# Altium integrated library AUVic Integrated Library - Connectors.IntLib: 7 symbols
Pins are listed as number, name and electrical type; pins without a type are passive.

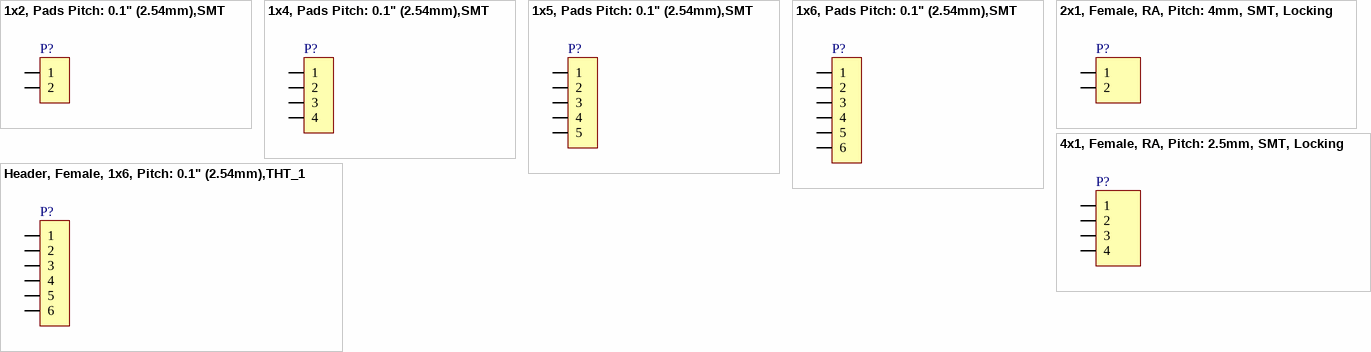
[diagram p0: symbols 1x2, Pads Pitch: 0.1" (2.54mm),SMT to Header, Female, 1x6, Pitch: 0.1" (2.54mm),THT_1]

## 1x2, Pads Pitch: 0.1" (2.54mm),SMT
designator P?  (value not drawn)  (no BOM)
1x2, Pads Pitch: 0.1" (2.54mm),SMT
footprint 1x2, Pads Pitch: 0.1" (2.54mm),SMT
pins: 1, 2

## 1x4, Pads Pitch: 0.1" (2.54mm),SMT
designator P?  (value not drawn)  (no BOM)
1x4, Pads Pitch: 0.1" (2.54mm),SMT
footprint 1x4, Pads Pitch: 0.1" (2.54mm),SMT
pins: 1, 2, 3, 4

## 1x5, Pads Pitch: 0.1" (2.54mm),SMT
designator P?  (value not drawn)  (no BOM)
1x5, Pads Pitch: 0.1" (2.54mm),SMT
footprint 1x5, Pads Pitch: 0.1" (2.54mm),SMT
pins: 1, 2, 3, 4, 5

## 1x6, Pads Pitch: 0.1" (2.54mm),SMT
designator P?  (value not drawn)  (no BOM)
1x6, Pads Pitch: 0.1" (2.54mm),SMT
footprint 1x6, Pads Pitch: 0.1" (2.54mm),SMT
pins: 1, 2, 3, 4, 5, 6

## 2x1, Female, RA, Pitch: 4mm, SMT, Locking
designator P?  (value not drawn)
2x1 Female, RA, Pitch: 4mm, SMT, Locking
footprint 2x1, Female, RA, Pitch: 4mm, SMT, Locking
pins: 1, 2

## 4x1, Female, RA, Pitch: 2.5mm, SMT, Locking
designator P?  (value not drawn)
4x1 Female, RA, Pitch: 2.5mm, SMT, Locking; Owner: AUVic
footprint 4x1 Female, RA, Pitch: 2.5mm, SMT, Locking
pins: 1, 2, 3, 4

## Header, Female, 1x6, Pitch: 0.1" (2.54mm),THT_1
designator P?  (value not drawn)
Header, Female, 1x6, Pitch: 0.1" (2.54mm),THT
footprint Header, Female, 1x6, Pitch: 0.1" (2.54mm),THT
pins: 1, 2, 3, 4, 5, 6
